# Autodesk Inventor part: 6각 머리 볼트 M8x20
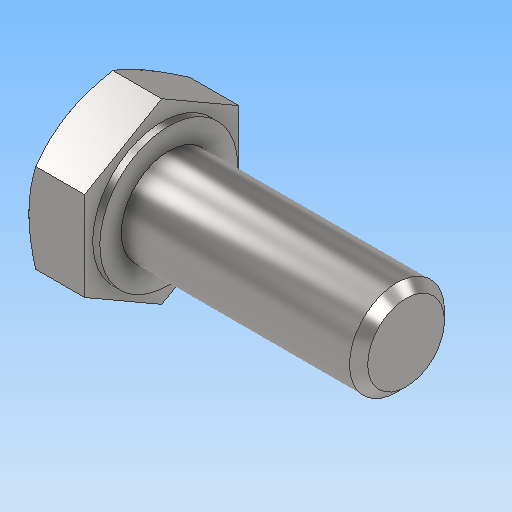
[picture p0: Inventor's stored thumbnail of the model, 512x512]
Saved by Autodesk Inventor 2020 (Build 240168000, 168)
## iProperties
Created: 2025-11
Part Number: 6각 머리 볼트 M8x20
Material: 강철, 연강
Description: 6각 머리 볼트 및 6각 머리 나사
Document SubType Name: Modeling
Designer: PC2-06
Density: 7.85 g/cm^3
Appearance: 기본값
Author: jhkim
Sending System: Autodesk Inventor 2026
Preprocessor: ST-DEVELOPER v20.1
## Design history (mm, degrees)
feature "Solid1"
node "솔리드1"
